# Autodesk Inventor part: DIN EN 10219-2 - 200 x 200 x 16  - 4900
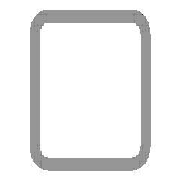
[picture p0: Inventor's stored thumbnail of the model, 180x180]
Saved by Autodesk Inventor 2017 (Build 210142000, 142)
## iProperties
IsCustomPart: 1
Created: 2017-11
Part Number: DIN EN 10219-2 - 200 x 200 x 16  - 4900
Material: Steel, Mild
Description: Cold formed welded structural hollow sections of non-alloy and fine grain structural steel
Document SubType Name: Modeling
Standard: DIN
Designer: iusti
Standard Revision: 2006-07
Standards Organization: DIN
Language: en-US
Size Designation: 200 x 200 x 16
Categories: <MemberInstance><Categories><Category DisplayName="Structural Shapes" InternalName="089c4875-fa83-4c05-b084-43b9cc11f5ed" Mnemonic="GRDR"><CategoryParameter Dis
Stock Number: 200 x 200 x 16
Density: 7.85 g/cm^3
Appearance: Semi-Polished
Mass: 410700 g
Surface Area: 65611.6 cm^2
Volume: 52318.5 cm^3
_CCFamilyMember: 103
_CCFamilyDisplayName: DIN EN 10219-2 (Square Hollow Section - Cold Formed) - Cold formed welded structural hollow sections of non-alloy and fine grain structural steel
_FrameMemberDoc: Frame Member File
_Version: 15.0.0
_GetPNFromCC: 1
G_L: 4900.000 mm
G_W: 200.000 mm
G_H: 200.000 mm
+6FBBBA41-A689-4153-B866-6340EAF31301+CUTDETAIL1: Cut
Author: iusti
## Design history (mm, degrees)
node "Start plane"
node "End plane"
sketch "Sketch"
  geometry: L1 (-100, -52)-(-100, 52); L2 (-52, 100)-(52, 100); L3 (100, 52)-(100, -52); L4 (52, -100)-(-52, -100); L5 (-52, 84)-(52, 84); L6 (84, 52)-(84, -52); L7 (52, -84)-(-52, -84); L8 (-84, -52)-(-84, 52); L9 (0, 293.918)-(0, -293.918) reference; L10 (-293.918, 0)-(293.918, 0) reference; A1 r 48 centre (-52, -52) between (-100, -52) and (-52, -100); A2 r 48 centre (-52, 52) between (-52, 100) and (-100, 52); A3 r 48 centre (52, 52) between (100, 52) and (52, 100); A4 r 48 centre (52, -52) between (52, -100) and (100, -52); A5 r 32 centre (-52, 52) between (-52, 84) and (-84, 52); A6 r 32 centre (52, 52) between (84, 52) and (52, 84); A7 r 32 centre (52, -52) between (52, -84) and (84, -52); A8 r 32 centre (-52, -52) between (-84, -52) and (-52, -84)
  constraints: 16 end point, 16 point on circle, 8 centre point, 8 tangent, 4 parallel, 3 equal radius, 2 perpendicular, 7 other
  dimensions: "d7" = 48 radius of A1 (= G_IR); "d10" = 200 distance between parallel lines of L2 L4 (= G_H); "d11" = 200 distance between parallel lines of L1 L3 (= G_W); "d12" = 16 distance between parallel lines of L3 L6 (= G_T); "d15" = 100 distance between parallel lines of L2 L10 (= 0.5 x d10); "d16" = 100 distance between parallel lines of L9 L3 (= 0.5 x d11)
extrude "Body" new body sketch "Sketch" stored distance "d3" = 4900 (= G_L); taper "d4" = 0 deg
node "Driven Length"
  sketch "Sketch3"
    geometry: L1 (0, 0)-(10, 0) reference
    constraints: 2 end point, 1 horizontal
  workplane "Work Plane3"
  sketch "Sketch4"
    geometry: L1 (-2, 0)-(12, 0) reference; L2 (-2, 4900)-(12, 4900) reference
    dimensions: "d18" = 4900 distance between parallel lines of L1 L2 (derived)
workplane "Work Plane4"
split "Split1"
body "Solid1"
other parameters: "G_W" = 200 [user parameter; used in 1 equation term], "G_H" = 200 [user parameter; used in 1 equation term], "G_T" = 16 [user parameter; used in 1 equation term], "G_IR" = 48 [user parameter; used in 1 equation term], "G_L" = 4900 (= d18) [user parameter; used in 1 equation term], "G_OFFSET_START" = 0 [user parameter; used in 1 equation term], "d13" = 0 (computed from G_OFFSET_START), "d17" = 90 deg
